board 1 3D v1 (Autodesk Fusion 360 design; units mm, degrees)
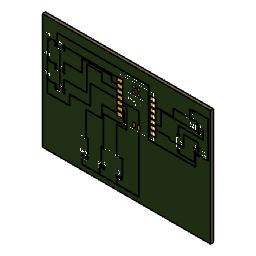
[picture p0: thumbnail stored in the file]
sketch "Outline" plane through (0, 0, 0) normal (0, 0, 1) x axis (1, 0, 0)
  line L1 (114.3, 44.45) -> (27.94, 44.45)
  line L2 (114.3, 103.81) -> (114.3, 44.45)
  line L3 (27.94, 103.81) -> (114.3, 103.81)
  line L4 (27.94, 44.45) -> (27.94, 103.81)
canvas "Canvas1"
canvas "Canvas2"
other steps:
base_feature "Base Feature1"
extrude "Extrude1" sketch "Outline" blind 1.5 bodies "Board"
pcbextrude "PCBExtrude1"
pcbextrude "PCBExtrude1"
pcbextrude "PCBExtrude1"
pcbextrude "PCBExtrude1"
base_feature "Base Feature1"
base_feature "Base Feature1"
box_primitive "BoxPrimitive1" DistanceX 20 DistanceY 18.89 DistanceZ 1 OffsetDistanceX 0 OffsetDistanceY 0
box_primitive "BoxPrimitive1" DistanceX 5 DistanceY 2.6 DistanceZ 0.99 OffsetDistanceX 0 OffsetDistanceY 0
base_feature "Base Feature1"
base_feature "Base Feature1"
pcbextrude "PCBExtrude1"
pcbhole "PCBHole1"
pcbhole "PCBHole1"
pcbextrude "PCBExtrude2" bodies "CopperHoles"
pcbhole "PCBHole2"
pcbhole "PCBHole2"
pcbhole "PCBHole1"
pcbhole "PCBHole2"
create_component "CreateComponent1"
create_component "CreateComponent2"
create_component "CreateComponent3"
create_component "CreateComponent4"
create_component "CreateComponent5"
create_component "CreateComponent6"
create_component "CreateComponent1"
create_component "CreateComponent2"
create_component "CreateComponent3"
create_component "CreateComponent4"
create_component "CreateComponent5"
create_component "CreateComponent1"
create_component "CreateComponent6"
as_built_joint "As-built1"
named bodies: "Board", "CopperHoles"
